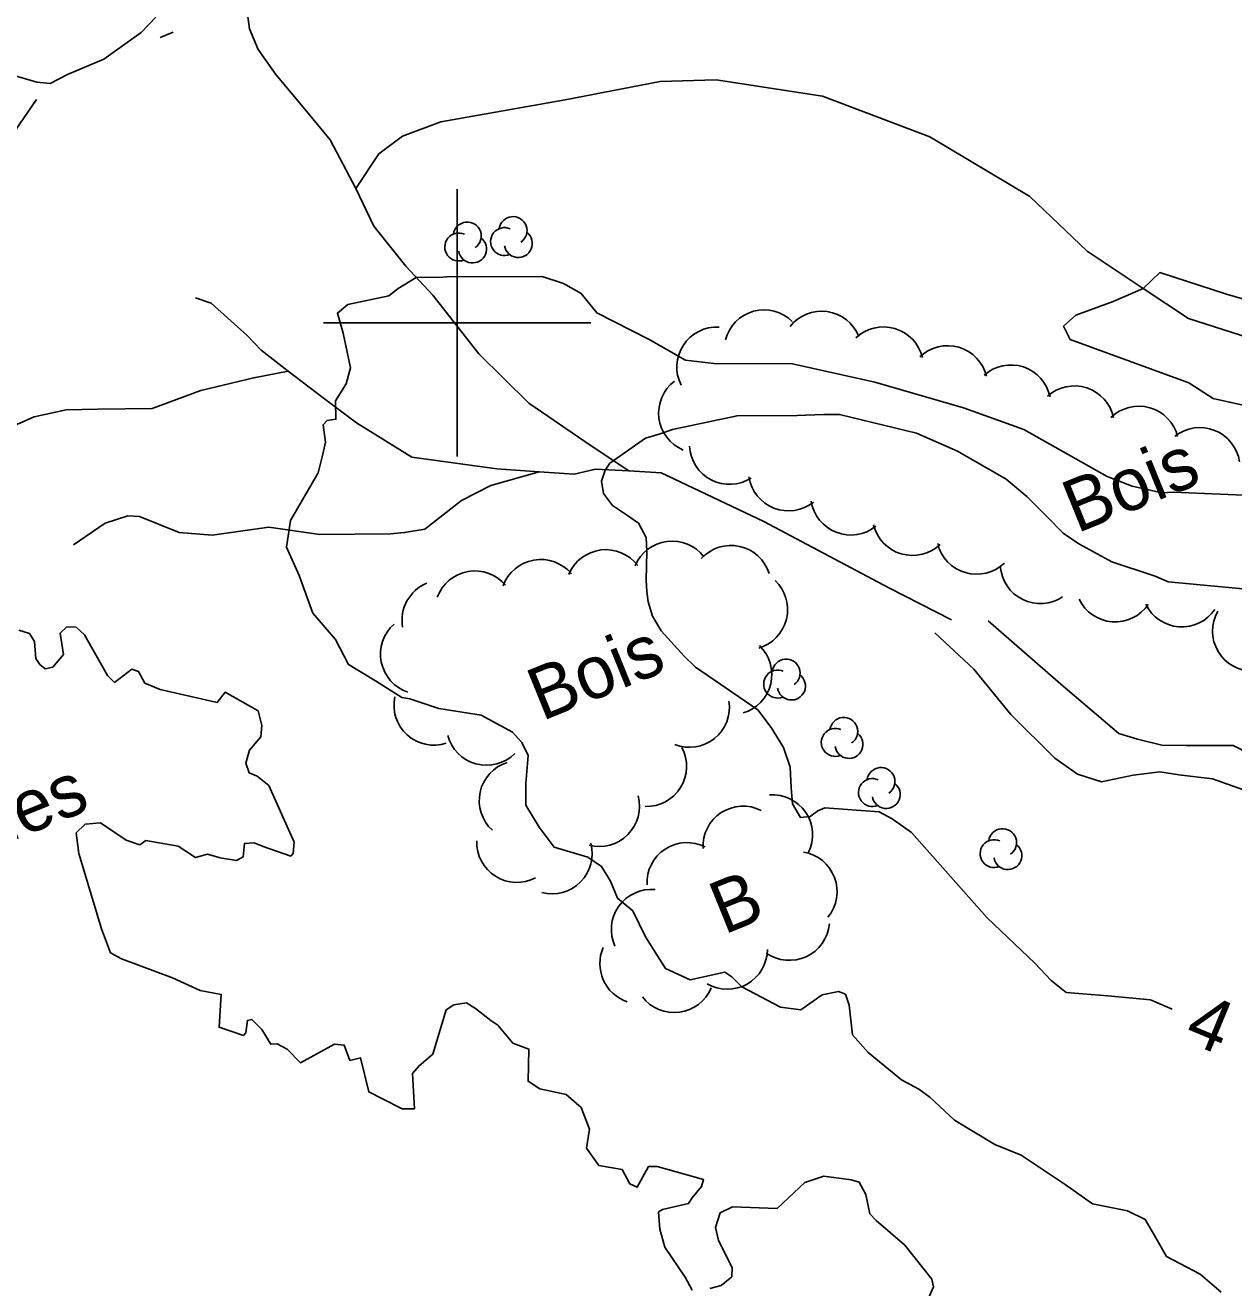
# Model space of a CAD drawing. Extents: x 362852 to 366875, y 5563573 to 5566479.
# Drawn here: x 363367.7 to 363458.1, y 5564327.8 to 5564422.3 of the extents above; entities that cross this region are included whole.
import ezdxf

# ---------------------------------------------------------------- set-up
doc = ezdxf.new("R2010")
doc.units = 0
for name, color, linetype in [('Niveau 19', 7, 'Continuous'), ('Niveau 2', 7, 'Continuous'), ('Niveau 22', 7, 'Continuous'), ('Niveau 3', 7, 'Continuous'), ('Niveau 4', 7, 'Continuous'), ('Niveau 44', 7, 'Continuous'), ('Niveau 61', 7, 'Continuous'), ('Niveau 7', 7, 'Continuous'), ('Niveau 8', 7, 'Continuous')]:
    doc.layers.add(name, color=color, linetype=linetype)

msp = doc.modelspace()

# ---------------------------------------------------------------- linework, layer by layer
at = {"layer": 'Niveau 19'}
for points in [[(363509.06, 5564333.7), (363505.59, 5564334.45), (363502.94, 5564335.43), (363500.05, 5564338.17), (363497.72, 5564340.42), (363493.45, 5564344.09), (363485.53, 5564350.06), (363480.77, 5564352.8), (363477, 5564355.2), (363471.28, 5564358.93), (363467.05, 5564363.01), (363465.18, 5564364.92), (363460.84, 5564366.96), (363458.09, 5564368.36), (363454.57, 5564368.36), (363452.73, 5564368.4), (363450.93, 5564368.83), (363449.52, 5564369.26), (363445.19, 5564372.96), (363439.75, 5564377.69)], [(363435.74, 5564376.79), (363438.67, 5564374.09), (363441.45, 5564370.7), (363444.72, 5564367.43), (363446.42, 5564366.21), (363448.22, 5564365.65), (363450.6, 5564366.14), (363452.6, 5564366.4), (363454, 5564366.18), (363456.53, 5564365.88), (363461.16, 5564364.23), (363463.23, 5564363.21), (363466.84, 5564360.18), (363472.56, 5564355.39), (363474.53, 5564353.83), (363479.87, 5564351.24), (363485.33, 5564347.1), (363493.13, 5564340.83), (363494.92, 5564339), (363498.61, 5564335.91), (363502.06, 5564333.42), (363504.82, 5564332.18), (363507.08, 5564331.56)]]:
    msp.add_lwpolyline(points, dxfattribs=at)
at = {"layer": 'Niveau 2'}
for points in [[(363414.37, 5564398.75), (363410.46, 5564400.74), (363409.29, 5564402.2), (363407.97, 5564402.96), (363406.37, 5564403.48), (363401.81, 5564403.44), (363399.48, 5564403.47), (363398.93, 5564403.42), (363396.94, 5564403.4), (363395.59, 5564402.58), (363394.88, 5564402.03), (363391.83, 5564401.38), (363391.04, 5564400.73), (363391.48, 5564399.23), (363392.01, 5564396.63), (363391.7, 5564395.43), (363390.91, 5564394.16), (363390.93, 5564392.79), (363390.27, 5564392.7), (363389.97, 5564392.38), (363390.14, 5564391.08), (363389.95, 5564390.18), (363389.6, 5564388.78), (363387.52, 5564385.21), (363387.24, 5564383.21), (363388.19, 5564381.1), (363389.19, 5564378.26), (363390.9, 5564376.29), (363391.86, 5564374.43), (363393.88, 5564373.21), (363395.85, 5564371.97), (363396.46, 5564371.85), (363398.64, 5564371.14), (363401.79, 5564370.64), (363404.15, 5564369.37), (363404.85, 5564368.6), (363405.32, 5564367.61), (363405.14, 5564365.52), (363405.13, 5564363.89), (363406.14, 5564362.25), (363407.26, 5564360.77), (363409.77, 5564360.01), (363410.81, 5564359.32), (363411.47, 5564358.21), (363412, 5564356.94), (363413.16, 5564355.98), (363414.09, 5564354.05), (363415.59, 5564351.67), (363417.45, 5564350.82)], [(363414.37, 5564398.75), (363417.09, 5564397.2), (363419.2, 5564396.95), (363425.11, 5564396.93), (363431.26, 5564395.56), (363437.89, 5564393.65), (363442.4, 5564392.03), (363448.64, 5564388.51), (363450.51, 5564387.79), (363452.73, 5564387.28)], [(363416.12, 5564392.03), (363420.95, 5564393.05), (363425.45, 5564393.06), (363427.42, 5564393.14), (363428.61, 5564393.14), (363434.39, 5564391.75), (363437.46, 5564390.41), (363441.09, 5564388.31), (363442.64, 5564387.01), (363444.14, 5564385.52), (363445.35, 5564384.27), (363446.52, 5564383.45), (363449.01, 5564382.12), (363452.23, 5564381.03), (363453.21, 5564380.62), (363459.07, 5564380.08)], [(363453.512, 5564348.633), (363451.89, 5564349.33), (363448.71, 5564349.62), (363445.59, 5564349.88), (363444.46, 5564350.78), (363443.23, 5564352.08), (363439.68, 5564355.47), (363434, 5564361.85), (363432.56, 5564362.87), (363431.59, 5564363.4), (363427.52, 5564363.7), (363426.99, 5564363.47), (363426.42, 5564363.05), (363425.69, 5564362.99), (363425.09, 5564363.99), (363425.01, 5564365.21), (363424.93, 5564366.74), (363424.43, 5564368.22), (363423.5, 5564369.71), (363422.5, 5564371.04), (363417.85, 5564374.22), (363417, 5564375.05), (363415.26, 5564376.95), (363414.61, 5564378.05), (363414.29, 5564379.11), (363414.21, 5564379.89), (363414.16, 5564380.75), (363414.2, 5564382.89), (363414.14, 5564383.93), (363413.57, 5564385), (363412.68, 5564385.63), (363411.64, 5564386.32), (363410.95, 5564387.22), (363410.8, 5564388.16), (363411.09, 5564388.97), (363411.43, 5564389.49), (363414.09, 5564391.36), (363415.2, 5564391.7), (363416.12, 5564392.03)], [(363452.73, 5564387.28), (363453.59, 5564387.32), (363459.45, 5564387.09)], [(363417.45, 5564350.82), (363420.03, 5564351.4), (363420.55, 5564351.06), (363421.31, 5564350.31), (363424.21, 5564348.77), (363425.72, 5564348.59), (363427.33, 5564349.7), (363428.54, 5564349.96), (363429.06, 5564349.75), (363429.35, 5564348.92), (363429.59, 5564346.71), (363430.77, 5564345.38), (363433.25, 5564343.35), (363434.55, 5564342.65), (363435.37, 5564342.05), (363437.22, 5564340.32), (363440.24, 5564338.51), (363442.21, 5564337.71), (363445.51, 5564335.52), (363447.56, 5564334.07), (363450.17, 5564333.53), (363451.5, 5564332.9), (363452.2, 5564331.69), (363453.1, 5564330.12), (363455.61, 5564328.79), (363457.17, 5564327.45)]]:
    msp.add_lwpolyline(points, dxfattribs=at)
at = {"layer": 'Niveau 22'}
for points in [[(363412.86, 5564388.92), (363410.03, 5564390.79), (363405.36, 5564394), (363401.63, 5564397.68), (363398.18, 5564402.07), (363396.15, 5564404.24), (363393.76, 5564407.25), (363392.42, 5564410.07), (363390.49, 5564413.71), (363388.73, 5564415.85), (363386.43, 5564418.58), (363385.1, 5564420.47), (363384.45, 5564422.01), (363384.08, 5564424.81), (363385.11, 5564427.44), (363388.1, 5564431.59), (363388.78, 5564434.01), (363388.83, 5564438.81), (363389.34, 5564440.59), (363393.45, 5564445.96)], [(363392.42, 5564410.07), (363394.13, 5564412.66), (363395.92, 5564413.98), (363398.79, 5564415.06), (363408.08, 5564416.7), (363415.19, 5564418.06), (363419.39, 5564418.2), (363427.35, 5564416.97), (363435.37, 5564413.92), (363442.85, 5564409.46), (363447.16, 5564405.37), (363451.35, 5564402.58), (363454.74, 5564400.33), (363459.26, 5564398.89), (363469.74, 5564396.53), (363478.32, 5564391.79), (363485.14, 5564389.26), (363494.49, 5564385.92), (363504.59, 5564381.07), (363516.12, 5564375.02)], [(363357.38, 5564388.52), (363357.3, 5564392.37), (363357.44, 5564397.45), (363358.3, 5564400.76), (363360, 5564404.25), (363361.58, 5564405.91), (363363.32, 5564406.89), (363364.33, 5564407.75), (363365.64, 5564409.49), (363366.99, 5564414.5), (363368.53, 5564416.71)], [(363412.86, 5564388.92), (363410.36, 5564389.06), (363408.76, 5564388.68), (363406.15, 5564388.86), (363402.96, 5564389.07), (363396.6, 5564389.96), (363392.48, 5564392.52), (363389.97, 5564394.38), (363387.36, 5564396.39), (363385.33, 5564397.95), (363384.28, 5564399.05), (363381.59, 5564401.48), (363380.42, 5564401.87)], [(363387.36, 5564396.39), (363384.78, 5564395.89), (363380.81, 5564394.94), (363377.18, 5564393.6), (363373.1, 5564393.53), (363370.75, 5564393.48), (363368.34, 5564392.97), (363364.87, 5564391.44), (363362.06, 5564390.45), (363359.09, 5564389.79), (363358.15, 5564389.53), (363357.38, 5564388.52), (363356.11, 5564385.98), (363354.61, 5564384.04), (363351.47, 5564380.64), (363348.74, 5564378.17), (363346.51, 5564377.36), (363344.95, 5564376.19), (363344.13, 5564375.6), (363342.92, 5564375.08), (363340.87, 5564374.73), (363339.72, 5564374.62)], [(363406.15, 5564388.86), (363402.52, 5564387.83), (363400.32, 5564386.71), (363397.59, 5564384.56), (363396.07, 5564384.3), (363394.98, 5564384.22), (363389.73, 5564384.16), (363385.9, 5564384.7), (363381.68, 5564384.11), (363379.19, 5564384.31), (363376.23, 5564385.51), (363375.36, 5564385.57), (363373.66, 5564385.02), (363371.3, 5564383.38)], [(363436.99, 5564377.77), (363432.31, 5564380.17), (363422.95, 5564385.14), (363415.27, 5564388.78), (363412.86, 5564388.92)]]:
    msp.add_lwpolyline(points, dxfattribs=at)
at = {"layer": 'Niveau 3'}
msp.add_line((363377.777, 5564421.372), (363378.741, 5564421.763), dxfattribs=at)
at = {"layer": 'Niveau 4'}
for points in [[(363377.44, 5564422.88), (363376.35, 5564421.74), (363373.55, 5564419.74), (363370.83, 5564418.6), (363369.54, 5564417.93), (363368.55, 5564418.02), (363366.26, 5564418.69)], [(363367.2, 5564376.99), (363367.99, 5564376.75), (363368.36, 5564376.16), (363368.46, 5564374.88), (363368.77, 5564374.44), (363369.16, 5564374.1), (363369.74, 5564374.22), (363370.53, 5564375.18), (363370.3, 5564376.78), (363370.8, 5564377.24), (363371.49, 5564377.22), (363372.11, 5564376.66), (363373.83, 5564373.61), (363374.36, 5564373.09), (363375.65, 5564374.07), (363376.16, 5564373.9), (363376.64, 5564373.04), (363377.78, 5564372.57), (363380.08, 5564372.03), (363382.03, 5564371.59), (363382.65, 5564372.36), (363385.12, 5564370.95), (363385.39, 5564369.86), (363385.31, 5564369.01), (363384.46, 5564368.03), (363384.19, 5564367.04), (363384.43, 5564366.32), (363385.04, 5564366.07), (363385.9, 5564365.37), (363387.8, 5564361.14), (363387.72, 5564360.29), (363387.55, 5564360.09), (363385.49, 5564360.8), (363384.81, 5564361.08), (363384.08, 5564361.02), (363383.99, 5564360.04), (363383.48, 5564359.76), (363382.27, 5564359.95), (363381.33, 5564360.24), (363380.43, 5564359.99), (363379.13, 5564360.83), (363376.7, 5564361.25), (363376.26, 5564360.94), (363375.24, 5564361.27), (363373.31, 5564362.59), (363372.16, 5564362.48), (363371.49, 5564361.83), (363371.7, 5564360.28), (363373.38, 5564354.64), (363374.07, 5564352.86), (363374.89, 5564352.39), (363378.69, 5564350.97), (363380.78, 5564350.02), (363382.35, 5564349.74), (363382.19, 5564347.28), (363384.01, 5564346.67), (363384.18, 5564346.86), (363384.3, 5564347.79), (363384.64, 5564347.87), (363385.39, 5564347.12), (363386.05, 5564346.01), (363386.54, 5564346.03), (363387.27, 5564345.65), (363388.27, 5564344.62), (363390.82, 5564346.01), (363391.55, 5564345.94), (363391.96, 5564344.79), (363392.76, 5564345), (363393.39, 5564342.44), (363394.42, 5564341.93), (363395.88, 5564341.16), (363396.81, 5564341.18), (363396.65, 5564343.81), (363397.15, 5564344.4), (363398.17, 5564345.27), (363399.17, 5564348.57), (363399.76, 5564348.95), (363400.71, 5564349.1)], [(363400.71, 5564349.1), (363401.38, 5564348.69), (363402.52, 5564347.78), (363403.04, 5564347.44), (363404.17, 5564346.09), (363405.36, 5564345.65), (363405.31, 5564343.24), (363406.18, 5564342.66), (363408.17, 5564342.24), (363409.28, 5564341.26), (363409.9, 5564339.64), (363409.67, 5564338.22), (363410.6, 5564336.92), (363412.35, 5564336.64), (363412.92, 5564335.57), (363413.48, 5564335.3), (363414.33, 5564336.85), (363414.96, 5564336.86), (363418.45, 5564335.88), (363418.28, 5564335.37), (363417.58, 5564334.51), (363417.32, 5564334.08), (363415.37, 5564333.64), (363415.07, 5564333.45), (363415.17, 5564332.17), (363415.54, 5564330.83), (363417.06, 5564328.57), (363417.59, 5564327.6)], [(363418.92, 5564327.72), (363419.77, 5564327.95), (363420.56, 5564328.6), (363420.58, 5564329.3), (363419.55, 5564331.31), (363419.33, 5564332.29), (363419.68, 5564333.38), (363420.62, 5564333.84), (363423.94, 5564333.72), (363424.79, 5564334.52), (363426.01, 5564335.66), (363427.44, 5564336.14), (363429.5, 5564335.87), (363430.09, 5564335.68), (363430.6, 5564334.76), (363430.89, 5564333.32), (363431.35, 5564332.82), (363433.51, 5564330.96), (363435.53, 5564328.41), (363435.64, 5564327.84), (363435, 5564326.37)]]:
    msp.add_lwpolyline(points, dxfattribs=at)
at = {"layer": 'Niveau 44'}
for centre, radius, start, end in [((363400.761, 5564406.501), 1.046, 304.35917, 171.81625), ((363404.187, 5564406.908), 1.046, 304.35917, 171.81625), ((363400.125, 5564405.678), 1.046, 66.20537, 291.89396), ((363403.55, 5564406.085), 1.046, 66.20537, 291.89396), ((363404.581, 5564405.938), 1.046, 189.02686, 51.71122), ((363401.155, 5564405.531), 1.046, 189.02686, 51.71122), ((363422.977, 5564397.976), 3, 45.38515, 165.36309), ((363427.278, 5564397.873), 3, 21.9253, 141.90325), ((363419.442, 5564396.688), 3, 86.80873, 206.78667), ((363431.906, 5564396.699), 3, 13.67982, 133.65777), ((363436.704, 5564395.292), 3, 13.67982, 133.65777), ((363441.438, 5564393.85), 3, 11.73312, 131.71106), ((363418.081, 5564393.25), 3, 127.21855, 247.19649), ((363446.185, 5564392.281), 3, 11.73312, 131.71106), ((363451.016, 5564390.762), 3, 14.20215, 134.18009), ((363455.585, 5564389.166), 3, 8.35623, 128.33418), ((363420.394, 5564390.913), 3, 182.62782, 302.60577), ((363424.802, 5564388.933), 3, 188.76159, 308.73953), ((363429.462, 5564387.12), 3, 188.76159, 308.73953), ((363434.082, 5564385.592), 3, 193.69967, 313.67761), ((363411.135, 5564380.026), 3, 37.43757, 157.41551), ((363416.093, 5564380.672), 3, 37.43757, 157.41551), ((363420.492, 5564380.342), 3, 17.62742, 137.60536), ((363438.881, 5564384.187), 3, 193.69967, 313.67761), ((363406.256, 5564379.291), 3, 39.91459, 159.89254), ((363401.331, 5564378.432), 3, 39.91459, 159.89254), ((363443.646, 5564381.987), 3, 183.90159, 303.87953), ((363398.878, 5564377.746), 3, 112.38429, 190.05696), ((363421.731, 5564378.538), 3, 286.37092, 46.34887), ((363449.25, 5564380.621), 3, 205.73219, 325.71013), ((363454.236, 5564380.247), 3, 205.73219, 325.71013), ((363459.538, 5564376.929), 3, 150.41888, 270.39683), ((363397.266, 5564375.201), 3, 131.43326, 251.41121), ((363420.551, 5564373.679), 3, 286.37092, 46.34887), ((363424.625, 5564373.788), 1.046, 304.35917, 171.81625), ((363423.988, 5564372.965), 1.046, 66.20537, 291.89396), ((363425.019, 5564372.819), 1.046, 189.02686, 51.71122), ((363398.273, 5564371.387), 3, 167.81859, 287.79653), ((363417.376, 5564371.232), 3, 248.81152, 8.78946), ((363428.299, 5564368.596), 1.046, 66.20537, 291.89396), ((363428.936, 5564369.419), 1.046, 304.35917, 171.81625), ((363402.195, 5564369.885), 3, 194.83046, 314.8084), ((363429.329, 5564368.449), 1.046, 189.02686, 51.71122), ((363414.179, 5564366.809), 3, 268.04159, 28.01953), ((363404.656, 5564364.243), 3, 107.71332, 227.69127), ((363431.083, 5564364.845), 1.046, 66.20537, 291.89396), ((363431.72, 5564365.668), 1.046, 304.35917, 171.81625), ((363432.113, 5564364.699), 1.046, 189.02686, 51.71122), ((363410.642, 5564363.812), 3, 255.09234, 15.07028), ((363423.603, 5564361.676), 3, 334.16184, 94.13978), ((363421.4, 5564360.828), 3, 63.07158, 183.04953), ((363440.824, 5564361.096), 1.046, 304.35917, 171.81625), ((363404.466, 5564361.118), 3, 177.91509, 297.89303), ((363417.209, 5564358.101), 3, 63.07158, 183.04953), ((363440.187, 5564360.273), 1.046, 66.20537, 291.89396), ((363407.11, 5564360.272), 3, 255.09234, 15.07028), ((363425.433, 5564357.428), 3, 320.66542, 80.64336), ((363441.217, 5564360.127), 1.046, 189.02686, 51.71122), ((363414.54, 5564354.6), 3, 84.65002, 204.62797), ((363424.871, 5564355.285), 3, 234.76415, 354.74209), ((363413.679, 5564352.035), 3, 156.26499, 251.30922), ((363420.221, 5564353.12), 3, 239.72752, 359.70547), ((363416.244, 5564351.374), 3, 217.44136, 337.4193)]:
    msp.add_arc(centre, radius, start, end, dxfattribs=at)
at = {"layer": 'Niveau 61'}
for p, q in [((363400, 5564410), (363400, 5564390)), ((363390, 5564400), (363410, 5564400))]:
    msp.add_line(p, q, dxfattribs=at)
at = {"layer": 'Niveau 7'}
msp.add_lwpolyline([(363462.75, 5564392.97), (363456.57, 5564394.34), (363454.76, 5564395.52), (363445.87, 5564398.75), (363445.39, 5564399.75), (363446.3, 5564400.57), (363449.1, 5564401.61), (363451.35, 5564402.58), (363452.6, 5564403.76), (363457.58, 5564402.14), (363460.07, 5564401.43)], dxfattribs=at)

# ---------------------------------------------------------------- texts
at = {"layer": 'Niveau 2'}
msp.add_text('4', height=3.93, rotation=337.50426, dxfattribs=at).set_placement((363454.28, 5564346.32))
at = {"layer": 'Niveau 44'}
for s, p in [('Bois', (363446.38, 5564384.23)), ('Bois', (363406.34, 5564370.17)), ('B', (363419.97, 5564354.19))]:
    msp.add_text(s, height=3.93, rotation=22.09, dxfattribs=at).set_placement(p)
at = {"layer": 'Niveau 8'}
msp.add_text('Îles', height=3.93, rotation=22.09, dxfattribs=at).set_placement((363365.09, 5564360.56))

doc.saveas('drawing.dxf')
